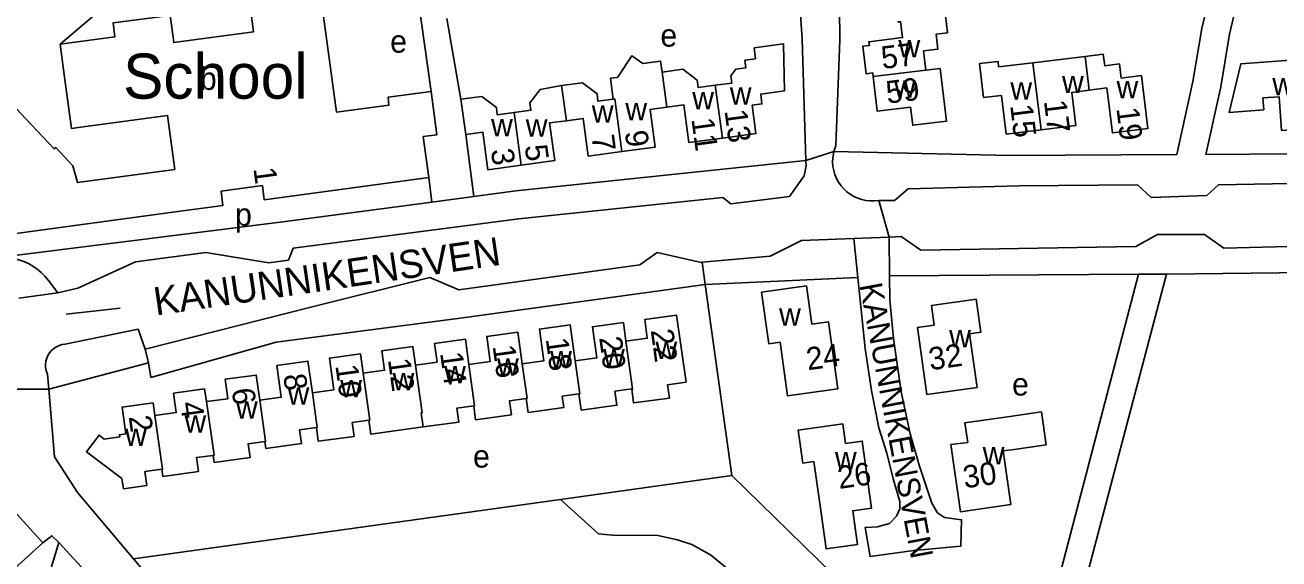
# Model space of a CAD drawing. Extents: x 162667 to 164645, y 379003 to 382150.
# Drawn here: x 163473.8 to 163696.1, y 380855.2 to 380949.9 of the extents above; entities that cross this region are included whole.
import ezdxf

# ---------------------------------------------------------------- set-up
doc = ezdxf.new("R2010")
doc.units = 0
for name, color, linetype in [('BLT_Basislijn', 7, 'Continuous'), ('BLT_Bebouwing', 7, 'Continuous'), ('BLT_Bebouwing_beschrifting', 7, 'Continuous'), ('BLT_Centroide', 7, 'Continuous'), ('BLT_Huisnummer', 7, 'Continuous'), ('BLT_Huisnummer_ tussenligend', 7, 'Continuous'), ('BLT_Onderverdeling_panden', 7, 'Continuous'), ('BLT_Straatnaam', 7, 'Continuous'), ('BLT_Straatnaam_verkleind', 7, 'Continuous'), ('BLT_Vlakafsluiter', 7, 'Continuous')]:
    doc.layers.add(name, color=color, linetype=linetype)

msp = doc.modelspace()

# ---------------------------------------------------------------- linework, layer by layer
at = {"layer": 'BLT_Basislijn'}
for p, q in [((163540.47, 380976.26), (163545.83, 380938.08)), ((163551.1, 380936.73), (163548.57, 380951.03)), ((163618.26, 380947.22), (163617.57, 380928.49)), ((163553.36, 380919.47), (163551.94, 380930.49)), ((163560.81, 380920.46), (163612.26, 380925.88)), ((163648.51, 380926.76), (163617.23, 380927.47)), ((163678.04, 380926.92), (163648.51, 380926.76)), ((163545.93, 380918.48), (163545.4, 380922.82)), ((163553.36, 380919.47), (163545.93, 380918.48)), ((163560.81, 380920.46), (163553.36, 380919.47)), ((163521.37, 380910.28), (163561.34, 380915.49)), ((163620.79, 380912.03), (163627.04, 380912.28)), ((163627.1, 380905.43), (163627.04, 380912.28)), ((163620.79, 380912.03), (163621.5, 380905.09)), ((163593.68, 380907.79), (163593.85, 380907.81)), ((163594.4, 380903.88), (163593.85, 380907.81)), ((163627.1, 380905.43), (163671.26, 380905.67)), ((163649.11, 380821.28), (163671.26, 380905.67)), ((163676.23, 380905.72), (163661.02, 380848.07)), ((163671.26, 380905.67), (163676.23, 380905.72)), ((163676.23, 380905.72), (163723.14, 380906.18)), ((163477.95, 380904.6), (163479.65, 380902.4)), ((163551.43, 380897.98), (163594.4, 380903.88)), ((163594.4, 380903.88), (163621.5, 380905.09)), ((163599.11, 380869.98), (163594.4, 380903.88)), ((163472.73, 380901.43), (163479.65, 380902.4)), ((163481.13, 380898.59), (163490.67, 380899.65)), ((163495.09, 380892.4), (163524.49, 380899.84)), ((163495.09, 380892.4), (163495.67, 380889.99)), ((163495.67, 380889.99), (163478, 380885.3)), ((163477.77, 380887.98), (163478, 380885.3)), ((163599.11, 380869.98), (163568.77, 380865.76)), ((163649.11, 380821.28), (163599.11, 380869.98)), ((163483.09, 380866.95), (163493.05, 380855.23)), ((163568.77, 380865.76), (163493.05, 380855.23)), ((163547.47, 380784.86), (163479.8, 380858.12))]:
    msp.add_line(p, q, dxfattribs=at)
for points in [[(163616.05, 380995.93), (163616.25, 380993.63), (163616.78, 380986.85), (163617.23, 380980.07), (163617.6, 380973.28), (163617.88, 380966.49), (163618.09, 380959.7), (163618.22, 380952.9), (163618.26, 380947.22)], [(163686.29, 380965.65), (163682.46, 380949.27), (163680.9, 380939.89), (163678.04, 380926.92)], [(163482.46, 380965.09), (163488.24, 380954.05), (163488.24, 380953.48), (163480.04, 380946.5)], [(163691.02, 380963.91), (163687.37, 380948.29), (163685.81, 380938.94), (163683.16, 380926.94)], [(163610.86, 380958.76), (163611.6, 380947.4), (163612.26, 380925.88)], [(163617.57, 380928.49), (163617.31, 380927.78), (163617.23, 380927.47)], [(163612.26, 380925.88), (163612.29, 380924.92), (163611.93, 380923.14), (163609.38, 380919.48), (163598.94, 380918.19)], [(163617.23, 380927.47), (163617.13, 380927.05), (163617.03, 380926.31), (163617.01, 380925.56), (163617.06, 380924.81), (163617.2, 380924.08), (163617.41, 380923.36), (163617.7, 380922.66), (163618.06, 380922.01), (163618.49, 380921.39), (163618.99, 380920.83), (163619.54, 380920.32), (163620.14, 380919.86), (163620.78, 380919.48), (163621.46, 380919.17), (163622.18, 380918.93), (163622.91, 380918.77), (163623.65, 380918.69), (163624.4, 380918.69), (163625.2, 380918.78)], [(163683.16, 380926.94), (163706.41, 380927.1), (163723.74, 380927.25)], [(163625.2, 380918.78), (163627.97, 380918.78), (163630.4, 380920.86), (163650.07, 380921.38)], [(163627.04, 380912.28), (163629.18, 380912.36), (163632.65, 380909.93), (163670.79, 380910.63), (163674.6, 380912.71), (163682.92, 380912.71), (163686.39, 380910.28), (163725.21, 380911.32), (163761.96, 380913.06), (163794.9, 380916.87), (163796.63, 380918.95), (163815.01, 380921.38), (163826.01, 380922.7), (163829.22, 380919.99)], [(163723.74, 380922.25), (163685.43, 380921.55), (163683.35, 380919.64), (163673.47, 380919.3), (163671.05, 380921.55), (163650.07, 380921.38)], [(163561.34, 380915.49), (163597.55, 380919.3), (163598.94, 380918.19)], [(163545.93, 380918.48), (163519.54, 380914.97), (163471.94, 380909.02)], [(163479.65, 380902.4), (163483.18, 380903.2), (163493.38, 380907.86), (163505.86, 380909.53), (163517.03, 380907.68), (163520.5, 380908.2), (163521.37, 380910.28)], [(163593.85, 380907.81), (163605.95, 380908.89), (163611.5, 380911.67), (163620.79, 380912.03)], [(163470.11, 380908.69), (163470.94, 380908.62), (163471.84, 380908.47), (163472.72, 380908.24), (163473.58, 380907.94), (163474.41, 380907.56), (163475.2, 380907.11), (163475.95, 380906.59), (163476.65, 380906.01), (163477.3, 380905.37), (163477.95, 380904.6)], [(163550.75, 380902.93), (163582.81, 380907.33), (163585.87, 380909.54), (163593.68, 380907.79)], [(163621.5, 380905.09), (163622.79, 380892.52), (163623.88, 380885.07), (163625.22, 380878.46), (163626.64, 380873.93), (163627.73, 380869.41), (163628.9, 380865.4), (163628.9, 380864.06), (163628.32, 380862.8), (163627.06, 380861.46), (163624.97, 380860.88), (163622.79, 380860.79), (163623.64, 380855.61), (163631.41, 380856.69), (163639.71, 380857.45), (163639.86, 380862.13), (163636.85, 380862.55), (163635.6, 380863.39), (163634.59, 380865.06), (163632.33, 380871.84), (163630.74, 380877.37), (163629.15, 380884.82), (163627.81, 380894.28), (163627.15, 380901.14), (163627.1, 380905.43)], [(163550.75, 380902.93), (163545.56, 380905.08), (163524.49, 380899.84)], [(163551.43, 380897.98), (163518.33, 380893.63), (163496.14, 380887.39), (163495.67, 380889.99)], [(163480.95, 380893.28), (163493.86, 380895.93), (163495.09, 380892.4)], [(163480.95, 380893.28), (163480.41, 380893.2), (163479.88, 380893.05), (163479.39, 380892.82), (163478.93, 380892.52), (163478.51, 380892.16), (163478.16, 380891.74), (163477.87, 380891.27), (163477.65, 380890.77), (163477.51, 380890.24), (163477.44, 380889.7), (163477.46, 380889.15), (163477.55, 380888.61), (163477.72, 380888.09), (163477.77, 380887.98)], [(163452.95, 380883.66), (163454.25, 380883.08), (163476.99, 380858.05)], [(163478, 380885.3), (163479.01, 380873.3), (163483.09, 380866.95)], [(163568.77, 380865.76), (163575.52, 380859.67), (163577.97, 380859.42), (163586.01, 380859.35), (163589.47, 380858.59), (163592.02, 380857.75), (163595.33, 380855.91), (163602.56, 380850)], [(163479.8, 380858.12), (163478.58, 380859.29), (163476.99, 380858.05)], [(163476.99, 380858.05), (163453.23, 380836.51), (163393.67, 380781.19), (163372.38, 380763.25), (163372.32, 380762.87), (163380.22, 380751.88), (163379.53, 380750.7), (163350, 380730.09)], [(163481.6, 380789.28), (163481.93, 380798.14), (163474.32, 380823.27), (163473.43, 380831.3), (163474.18, 380839.6), (163479.8, 380858.12)], [(163493.05, 380855.23), (163521.12, 380822.2), (163579.11, 380757.76), (163583.07, 380753.75)]]:
    msp.add_lwpolyline(points, dxfattribs=at)
at = {"layer": 'BLT_Bebouwing'}
for p, q in [((163551.94, 380930.49), (163551.1, 380936.73)), ((163553.36, 380882.35), (163553.7, 380879.89))]:
    msp.add_line(p, q, dxfattribs=at)
for points in [[(163480.04, 380946.5), (163489.75, 380947.81), (163489.42, 380950.25), (163499.53, 380951.59), (163500, 380948.13), (163500.19, 380946.76), (163514.34, 380948.68), (163513.42, 380955.58), (163511, 380955.26), (163509.99, 380962.9), (163517.64, 380963.94), (163517.95, 380961.54), (163525.24, 380962.5), (163525.91, 380957.55), (163529.01, 380934.45), (163538.34, 380935.69), (163538.17, 380937.06), (163545.83, 380938.08)], [(163624.18, 380940.76), (163624.12, 380941.38), (163622.93, 380941.24), (163622.35, 380946.12), (163623.53, 380946.26), (163623.42, 380946.93), (163629.4, 380947.66), (163629.06, 380950.47), (163628.85, 380950.44), (163628.63, 380950.41), (163628.61, 380950.57)], [(163637.01, 380951.59), (163637.39, 380948.5), (163635.34, 380948.25), (163635.66, 380945.63), (163633.14, 380945.32), (163633.55, 380941.9)], [(163484.09, 380931.82), (163482.05, 380931.54), (163480.71, 380941.55), (163480.04, 380946.5)], [(163602.72, 380935.66), (163604.48, 380935.89), (163604.25, 380937.65), (163608.46, 380938.21), (163608.32, 380946.55), (163603.07, 380945.81), (163603.32, 380943.9), (163601.44, 380943.65)], [(163578.12, 380936.74), (163577.62, 380940.44), (163578.85, 380940.6), (163581.41, 380944.42), (163583.35, 380943.07), (163586.51, 380943.5), (163586.78, 380941.55)], [(163596.19, 380939.19), (163599.11, 380939.59), (163598.93, 380940.9), (163599.82, 380942.06), (163601.61, 380942.3), (163601.44, 380943.65)], [(163652.51, 380943.19), (163646.44, 380942.45), (163646.33, 380943.42), (163643.06, 380943.03)], [(163661.78, 380944.32), (163652.51, 380943.19)], [(163665.25, 380942.66), (163665, 380944.71), (163661.78, 380944.32)], [(163701.59, 380941.41), (163701.59, 380941.41), (163701.41, 380943.91), (163689.39, 380943.02), (163687.3, 380934.38), (163693.45, 380934.85), (163693.3, 380936.96), (163696.17, 380937.17), (163696.61, 380931.2), (163702.33, 380931.62)], [(163586.78, 380941.55), (163590.42, 380942.04), (163593, 380940.1), (163593.17, 380938.78), (163596.19, 380939.19)], [(163633.55, 380941.9), (163636.07, 380942.16), (163636.49, 380938.74), (163637.21, 380932.86), (163631.22, 380932.12), (163630.83, 380935.31), (163624.93, 380934.59), (163624.18, 380940.76)], [(163643.06, 380943.03), (163643.77, 380937.02)], [(163665.63, 380938.72), (163666.62, 380930.74), (163672.92, 380931.52), (163671.76, 380940.91), (163668.19, 380940.47), (163667.87, 380942.99), (163665.25, 380942.66)], [(163560.53, 380934.36), (163563.5, 380934.76), (163563.32, 380936.08), (163565.13, 380938.44), (163568.91, 380939.14)], [(163568.91, 380939.14), (163572.65, 380939.64), (163575.23, 380937.69), (163575.4, 380936.37), (163578.12, 380936.74)], [(163459.27, 380931.78), (163461.97, 380928.92), (163470.54, 380936.92), (163473.96, 380933.27), (163479, 380927.9), (163479.28, 380928.15), (163482.3, 380924.91), (163483.11, 380921.94), (163500.36, 380924.27), (163499.08, 380933.84), (163484.09, 380931.82)], [(163545.4, 380922.82), (163544.43, 380930.11), (163546.85, 380930.43), (163546.19, 380935.39), (163545.83, 380938.08)], [(163551.1, 380936.73), (163554.8, 380937.23), (163557.38, 380935.28), (163557.55, 380933.96), (163560.53, 380934.36)], [(163643.77, 380937.02), (163646.93, 380937.41)], [(163646.93, 380937.41), (163647.79, 380930.54), (163653.96, 380931.31)], [(163653.96, 380931.31), (163660.12, 380932.07), (163659.39, 380937.94), (163662.52, 380938.33)], [(163662.52, 380938.33), (163665.63, 380938.72)], [(163587.62, 380935.33), (163584.65, 380934.92), (163585.56, 380928.23), (163579.62, 380927.43)], [(163597.45, 380929.84), (163591.51, 380929.04), (163590.6, 380935.73), (163587.62, 380935.33)], [(163602.72, 380935.66), (163603.39, 380930.64), (163597.45, 380929.84)], [(163569.81, 380932.92), (163566.83, 380932.52), (163567.73, 380925.83), (163561.8, 380925.03)], [(163579.62, 380927.43), (163573.68, 380926.63), (163572.78, 380933.32), (163569.81, 380932.92)], [(163561.8, 380925.03), (163555.86, 380924.22), (163554.96, 380930.9), (163551.94, 380930.49)], [(163545.4, 380922.82), (163516.23, 380918.87), (163515.89, 380921.4), (163508.56, 380920.41), (163508.9, 380917.88), (163500, 380916.68), (163471.33, 380912.8)], [(163604.42, 380902.5), (163605.7, 380893.34), (163607.68, 380893.62), (163609.01, 380884.11), (163617.92, 380885.36), (163616.26, 380897.25), (163613.29, 380896.84), (163612.35, 380903.6), (163604.42, 380902.5)], [(163642.45, 380901.24), (163634.53, 380900.13), (163635.02, 380896.66), (163632.04, 380896.24), (163633.71, 380884.35), (163642.63, 380885.6), (163641.29, 380895.11), (163643.27, 380895.39), (163642.45, 380901.24)], [(163571.37, 380890.3), (163570.48, 380896.71), (163565, 380895.96), (163565.78, 380890.32), (163561.96, 380889.8)], [(163580.35, 380893.82), (163579.9, 380897.12), (163574.4, 380896.36), (163575.17, 380890.83), (163571.37, 380890.3)], [(163581.38, 380885.34), (163581.72, 380882.86), (163588.06, 380883.73), (163587.73, 380886.09), (163591.01, 380886.55), (163589.34, 380898.42), (163583.68, 380897.64), (163584.14, 380894.34), (163580.35, 380893.82)], [(163561.96, 380889.8), (163561.18, 380895.43), (163555.69, 380894.67), (163556.3, 380890.23), (163552.5, 380889.7)], [(163543.04, 380889.58), (163542.58, 380892.86), (163537.08, 380892.1), (163537.56, 380888.65), (163533.75, 380888.13)], [(163552.5, 380889.7), (163551.88, 380894.15), (163546.4, 380893.39), (163546.86, 380890.1), (163543.04, 380889.58)], [(163524.75, 380884.63), (163523.96, 380890.28), (163518.46, 380889.52), (163519.23, 380883.86), (163515.44, 380883.35)], [(163533.75, 380888.13), (163533.27, 380891.58), (163527.77, 380890.82), (163528.56, 380885.16), (163524.75, 380884.63)], [(163515.44, 380883.35), (163514.8, 380887.8), (163509.31, 380887.05), (163509.74, 380883.57), (163505.96, 380883.1)], [(163505.96, 380883.1), (163505.65, 380885.34), (163500.16, 380884.58), (163500.62, 380881.16), (163496.84, 380880.65)], [(163553.7, 380879.89), (163560.04, 380880.76), (163559.7, 380883.24), (163562.67, 380883.65)], [(163562.67, 380883.65), (163563.01, 380881.18), (163569.33, 380882.05), (163569.06, 380884.04), (163572.03, 380884.45)], [(163572.03, 380884.45), (163572.42, 380881.58), (163578.76, 380882.45), (163578.41, 380884.93), (163581.38, 380885.34)], [(163496.84, 380880.65), (163496.52, 380882.86), (163491.02, 380882.11), (163491.67, 380877.39), (163490.54, 380877.23), (163490.59, 380876.82), (163487.86, 380876.44), (163486.93, 380877.15), (163484.7, 380874.21), (163490.98, 380869.44), (163491.25, 380867.65), (163495.41, 380868.22), (163495.07, 380870.69), (163498.05, 380871.1)], [(163544.41, 380878.61), (163550.73, 380879.47), (163550.39, 380881.94), (163553.36, 380882.35)], [(163648.4, 380880.47), (163640.47, 380879.35), (163640.96, 380875.87), (163637.99, 380875.46), (163639.67, 380863.57), (163648.58, 380864.83), (163647.24, 380874.35), (163649.22, 380874.63), (163654.85, 380875.42), (163654.02, 380881.26), (163648.4, 380880.47)], [(163525.47, 380878.51), (163525.81, 380876.05), (163532.14, 380876.92), (163531.8, 380879.38), (163534.78, 380879.79)], [(163534.78, 380879.79), (163535.12, 380877.33), (163544.41, 380878.61)], [(163610.89, 380878.03), (163611.7, 380872.19), (163613.68, 380872.46), (163615.01, 380862.96), (163615.85, 380856.97), (163621.4, 380857.75), (163620.56, 380863.73), (163623.92, 380864.2), (163622.26, 380876.1), (163619.29, 380875.68), (163618.81, 380879.14), (163610.89, 380878.03)], [(163516.33, 380876.03), (163516.51, 380874.77), (163522.84, 380875.64), (163522.5, 380878.1), (163525.47, 380878.51)], [(163507.18, 380873.56), (163507.35, 380872.29), (163513.7, 380873.16), (163513.36, 380875.62), (163516.33, 380876.03)], [(163498.05, 380871.1), (163498.22, 380869.83), (163504.54, 380870.7), (163504.21, 380873.16), (163507.18, 380873.56)]]:
    msp.add_lwpolyline(points, dxfattribs=at)
at = {"layer": 'BLT_Onderverdeling_panden'}
for p, q in [((163652.51, 380943.19), (163653.96, 380931.31)), ((163587.62, 380935.33), (163586.78, 380941.55)), ((163624.18, 380940.76), (163633.55, 380941.9)), ((163569.81, 380932.92), (163568.91, 380939.14)), ((163597.45, 380929.84), (163596.19, 380939.19)), ((163561.8, 380925.03), (163560.53, 380934.36))]:
    msp.add_line(p, q, dxfattribs=at)
for points in [[(163661.78, 380944.32), (163662.52, 380938.33)], [(163579.62, 380927.43), (163578.38, 380936.78), (163578.12, 380936.74)], [(163581.38, 380885.34), (163581.53, 380885.36), (163580.35, 380893.82)], [(163572.03, 380884.45), (163572.18, 380884.47), (163571.37, 380890.3)], [(163534.78, 380879.79), (163534.92, 380879.81), (163533.75, 380888.13)], [(163544.41, 380878.61), (163544.07, 380881.07), (163544.22, 380881.09), (163543.04, 380889.58)], [(163553.36, 380882.35), (163553.51, 380882.37), (163552.5, 380889.7)], [(163562.67, 380883.65), (163562.82, 380883.67), (163561.96, 380889.8)], [(163516.33, 380876.03), (163516.47, 380876.05), (163515.44, 380883.35)], [(163525.47, 380878.51), (163525.61, 380878.53), (163524.75, 380884.63)], [(163507.18, 380873.56), (163507.32, 380873.58), (163505.96, 380883.1)], [(163498.05, 380871.1), (163498.19, 380871.12), (163496.84, 380880.65)]]:
    msp.add_lwpolyline(points, dxfattribs=at)
at = {"layer": 'BLT_Vlakafsluiter'}
for p, q in [((163612.26, 380925.88), (163617.23, 380927.47)), ((163625.2, 380918.78), (163627.04, 380912.28)), ((163478, 380885.3), (163472.12, 380885.32))]:
    msp.add_line(p, q, dxfattribs=at)

# ---------------------------------------------------------------- texts
at = {"layer": 'BLT_Bebouwing_beschrifting'}
msp.add_text('School', height=8, dxfattribs=at).set_placement((163491.2, 380936.82))
at = {"layer": 'BLT_Centroide'}
for s, p in [('e', (163538.55, 380944.98)), ('e', (163586.47, 380946.05)), ('w', (163628.67, 380944.14)), ('b', (163504.8, 380938.38)), ('w', (163598.77, 380935.78)), ('w', (163627.88, 380937)), ('w', (163648.52, 380936.66)), ('w', (163657.67, 380937.8)), ('w', (163667.34, 380936.89)), ('w', (163694.96, 380937.44)), ('w', (163592.11, 380934.94)), ('w', (163574.3, 380932.55)), ('w', (163580.25, 380932.97)), ('w', (163556.44, 380930.14)), ('w', (163562.59, 380930.09)), ('p', (163511.05, 380914.28)), ('w', (163607.51, 380896.55)), ('w', (163637.66, 380892.73)), ('w', (163566.91, 380888.97)), ('w', (163576.3, 380889.38)), ('w', (163585.59, 380890.66)), ('w', (163557.5, 380887.69)), ('w', (163538.98, 380885.12)), ('w', (163548.12, 380886.36)), ('w', (163520.36, 380882.55)), ('w', (163529.69, 380883.84)), ('e', (163648.82, 380884.17)), ('w', (163511.2, 380880.06)), ('w', (163502.08, 380877.61)), ('w', (163491.54, 380875.25)), ('e', (163553.25, 380871.39)), ('w', (163643.61, 380871.95)), ('w', (163617.41, 380871.11))]:
    msp.add_text(s, height=4, dxfattribs=at).set_placement(p)
at = {"layer": 'BLT_Huisnummer'}
for s, rotation, p in [('59', 6.9621, (163626.7, 380935.92)), ('13', 277.6961, (163597.82, 380934.69)), ('15', 277.0652, (163648.47, 380935.63)), ('17', 277.0674, (163654.46, 380936.41)), ('19', 277.0617, (163667.31, 380935.1)), ('9', 277.7499, (163580.14, 380930.95)), ('3', 277.6974, (163556.4, 380927.74)), ('1', 277.6493, (163514.29, 380924.44)), ('22', 277.8221, (163584.74, 380895.76)), ('18', 277.8221, (163566.12, 380894.21)), ('24', 7.9599, (163612.61, 380888.64)), ('32', 8.0014, (163634.32, 380888.64)), ('14', 277.8221, (163547.39, 380891.7)), ('10', 277.8221, (163528.83, 380889.47)), ('6', 277.8221, (163510.44, 380885.27)), ('2', 277.8221, (163492.18, 380880.43)), ('26', 7.9599, (163618.16, 380867.6)), ('30', 8.023, (163640.41, 380867.7))]:
    msp.add_text(s, height=4, rotation=rotation, dxfattribs=at).set_placement(p)
at = {"layer": 'BLT_Huisnummer_ tussenligend'}
for s, rotation, p in [('57', 6.9621, (163625.85, 380942.07)), ('11', 277.7499, (163591.95, 380933.21)), ('7', 277.6574, (163574.24, 380930.2)), ('5', 277.6574, (163562.39, 380928.46)), ('20', 277.8221, (163575.6, 380894.44)), ('16', 277.8221, (163556.7, 380892.94)), ('12', 277.8221, (163538.14, 380890.57)), ('8', 277.8221, (163519.59, 380887.8)), ('4', 277.8221, (163501.29, 380882.87))]:
    msp.add_text(s, height=4, rotation=rotation, dxfattribs=at).set_placement(p)
at = {"layer": 'BLT_Straatnaam'}
msp.add_text('KANUNNIKENSVEN', height=5, rotation=8.3747, dxfattribs=at).set_placement((163497, 380898.34))
at = {"layer": 'BLT_Straatnaam_verkleind'}
msp.add_text('KANUNNIKENSVEN', height=4, rotation=280.6942, dxfattribs=at).set_placement((163621.75, 380903.78))

doc.saveas('drawing.dxf')
